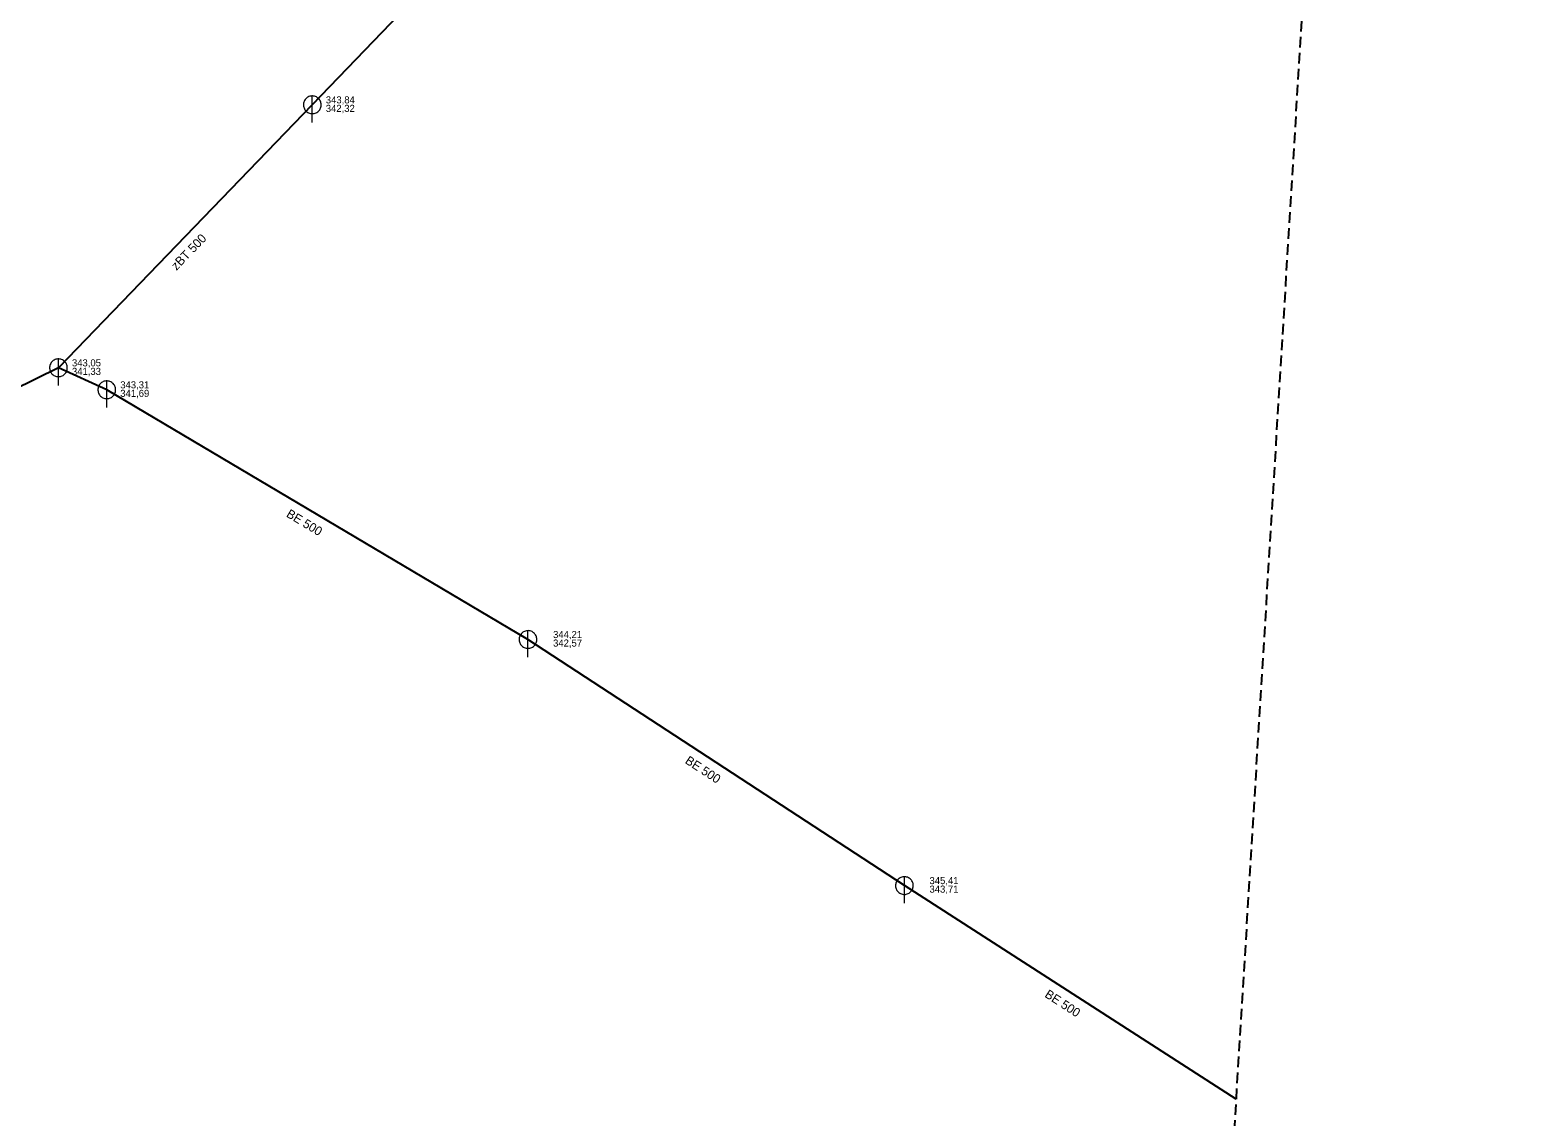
# Model space of a CAD drawing. Extents: x -724325 to -723665, y -972119 to -970722.
# Drawn here: x -724005.4 to -723835.3, y -971052.4 to -970929.9 of the extents above; entities that cross this region are included whole.
import ezdxf

# ---------------------------------------------------------------- set-up
doc = ezdxf.new("R2010")
doc.units = 0
doc.header["$LTSCALE"] = 0.4
doc.linetypes.add('MEDIUM_DASHED', pattern=[4.5, 3, -1.5])
for name, color, linetype, lineweight in [('1', 7, 'Continuous', 25), ('14', 7, 'Continuous', 25), ('22', 7, 'Continuous', 13)]:
    doc.layers.add(name, color=color, linetype=linetype, lineweight=lineweight)
doc.layers.add('19', color=7, linetype='Continuous')

msp = doc.modelspace()

# ---------------------------------------------------------------- linework, layer by layer
at = {"layer": '1', "linetype": 'MEDIUM_DASHED'}
msp.add_lwpolyline([(-724178.033, -970726.408), (-723849.368, -970722.221), (-723876.582, -971170.211), (-723665.148, -971503.063), (-723686.082, -972118.833), (-723917.752, -972118.833), (-723962.412, -971393.118), (-724325.27, -971133.535)], close=True, dxfattribs=at)
at = {"layer": '14'}
for p, q in [((-723942.149, -970905.61), (-723973.52, -970938.289)), ((-723973.52, -970938.289), (-724002.16, -970967.949)), ((-723996.71, -970970.43), (-724002.16, -970967.949)), ((-723949.19, -970998.59), (-723996.71, -970970.43)), ((-723906.719, -971026.34), (-723949.19, -970998.59)), ((-723869.306, -971050.437), (-723906.719, -971026.34))]:
    msp.add_line(p, q, dxfattribs=at)
msp.add_lwpolyline([(-724002.16, -970967.949), (-724038.379, -970985.76), (-724040.368, -970986.355)], dxfattribs=at)
at = {"layer": '22'}
for p, q in [((-723973.52, -970940.289), (-723973.519, -970937.289)), ((-724002.16, -970969.949), (-724002.159, -970966.949)), ((-723996.71, -970972.43), (-723996.709, -970969.43)), ((-723949.19, -971000.59), (-723949.189, -970997.59)), ((-723906.719, -971028.34), (-723906.718, -971025.34))]:
    msp.add_line(p, q, dxfattribs=at)
for points in [[(-723972.52, -970938.289), (-723972.525, -970938.18), (-723972.543, -970938.072), (-723972.573, -970937.966), (-723972.613, -970937.865), (-723972.665, -970937.768), (-723972.727, -970937.678), (-723972.799, -970937.595), (-723972.879, -970937.521), (-723972.967, -970937.455), (-723973.061, -970937.4), (-723973.161, -970937.355), (-723973.266, -970937.322), (-723973.373, -970937.3), (-723973.482, -970937.29), (-723973.592, -970937.292), (-723973.7, -970937.306), (-723973.807, -970937.331), (-723973.91, -970937.368), (-723974.008, -970937.417), (-723974.1, -970937.475), (-723974.186, -970937.544), (-723974.263, -970937.621), (-723974.332, -970937.707), (-723974.391, -970937.799), (-723974.439, -970937.897), (-723974.476, -970938), (-723974.502, -970938.107), (-723974.516, -970938.215), (-723974.519, -970938.325), (-723974.509, -970938.434), (-723974.488, -970938.541), (-723974.454, -970938.645), (-723974.41, -970938.745), (-723974.355, -970938.84), (-723974.289, -970938.928), (-723974.215, -970939.008), (-723974.132, -970939.08), (-723974.042, -970939.142), (-723973.946, -970939.194), (-723973.844, -970939.235), (-723973.739, -970939.265), (-723973.631, -970939.283), (-723973.521, -970939.289), (-723973.412, -970939.283), (-723973.304, -970939.265), (-723973.199, -970939.236), (-723973.097, -970939.195), (-723973, -970939.143), (-723972.91, -970939.081), (-723972.827, -970939.01), (-723972.752, -970938.93), (-723972.687, -970938.842), (-723972.631, -970938.748), (-723972.587, -970938.648), (-723972.553, -970938.544), (-723972.531, -970938.436), (-723972.521, -970938.327)], [(-724001.16, -970967.949), (-724001.165, -970967.84), (-724001.183, -970967.732), (-724001.213, -970967.626), (-724001.253, -970967.525), (-724001.305, -970967.428), (-724001.367, -970967.338), (-724001.439, -970967.255), (-724001.519, -970967.181), (-724001.607, -970967.115), (-724001.701, -970967.06), (-724001.801, -970967.015), (-724001.906, -970966.982), (-724002.013, -970966.96), (-724002.122, -970966.95), (-724002.232, -970966.952), (-724002.34, -970966.966), (-724002.447, -970966.991), (-724002.55, -970967.028), (-724002.648, -970967.077), (-724002.74, -970967.135), (-724002.826, -970967.204), (-724002.903, -970967.281), (-724002.972, -970967.367), (-724003.031, -970967.459), (-724003.079, -970967.557), (-724003.116, -970967.66), (-724003.142, -970967.767), (-724003.156, -970967.875), (-724003.159, -970967.985), (-724003.149, -970968.094), (-724003.128, -970968.201), (-724003.094, -970968.305), (-724003.05, -970968.405), (-724002.995, -970968.5), (-724002.929, -970968.588), (-724002.855, -970968.668), (-724002.772, -970968.74), (-724002.682, -970968.802), (-724002.586, -970968.854), (-724002.484, -970968.895), (-724002.379, -970968.925), (-724002.271, -970968.943), (-724002.161, -970968.949), (-724002.052, -970968.943), (-724001.944, -970968.925), (-724001.839, -970968.896), (-724001.737, -970968.855), (-724001.64, -970968.803), (-724001.55, -970968.741), (-724001.467, -970968.67), (-724001.392, -970968.59), (-724001.327, -970968.502), (-724001.271, -970968.408), (-724001.227, -970968.308), (-724001.193, -970968.204), (-724001.171, -970968.096), (-724001.161, -970967.987)], [(-723995.71, -970970.43), (-723995.715, -970970.321), (-723995.733, -970970.213), (-723995.763, -970970.107), (-723995.803, -970970.006), (-723995.855, -970969.909), (-723995.917, -970969.819), (-723995.989, -970969.736), (-723996.069, -970969.662), (-723996.157, -970969.596), (-723996.251, -970969.541), (-723996.351, -970969.496), (-723996.456, -970969.463), (-723996.563, -970969.441), (-723996.672, -970969.431), (-723996.782, -970969.433), (-723996.89, -970969.447), (-723996.997, -970969.472), (-723997.1, -970969.509), (-723997.198, -970969.558), (-723997.29, -970969.616), (-723997.376, -970969.685), (-723997.453, -970969.762), (-723997.522, -970969.848), (-723997.581, -970969.94), (-723997.629, -970970.038), (-723997.666, -970970.141), (-723997.692, -970970.248), (-723997.706, -970970.356), (-723997.709, -970970.466), (-723997.699, -970970.575), (-723997.678, -970970.682), (-723997.644, -970970.786), (-723997.6, -970970.886), (-723997.545, -970970.981), (-723997.479, -970971.069), (-723997.405, -970971.149), (-723997.322, -970971.221), (-723997.232, -970971.283), (-723997.136, -970971.335), (-723997.034, -970971.376), (-723996.929, -970971.406), (-723996.821, -970971.424), (-723996.711, -970971.43), (-723996.602, -970971.424), (-723996.494, -970971.406), (-723996.389, -970971.377), (-723996.287, -970971.336), (-723996.19, -970971.284), (-723996.1, -970971.222), (-723996.017, -970971.151), (-723995.942, -970971.071), (-723995.877, -970970.983), (-723995.821, -970970.889), (-723995.777, -970970.789), (-723995.743, -970970.685), (-723995.721, -970970.577), (-723995.711, -970970.468)], [(-723948.19, -970998.59), (-723948.195, -970998.481), (-723948.213, -970998.373), (-723948.243, -970998.267), (-723948.283, -970998.166), (-723948.335, -970998.069), (-723948.397, -970997.979), (-723948.469, -970997.896), (-723948.549, -970997.822), (-723948.637, -970997.756), (-723948.731, -970997.701), (-723948.831, -970997.656), (-723948.936, -970997.623), (-723949.043, -970997.601), (-723949.152, -970997.591), (-723949.262, -970997.593), (-723949.37, -970997.607), (-723949.477, -970997.632), (-723949.58, -970997.669), (-723949.678, -970997.718), (-723949.77, -970997.776), (-723949.856, -970997.845), (-723949.933, -970997.922), (-723950.002, -970998.008), (-723950.061, -970998.1), (-723950.109, -970998.198), (-723950.146, -970998.301), (-723950.172, -970998.408), (-723950.186, -970998.516), (-723950.189, -970998.626), (-723950.179, -970998.735), (-723950.158, -970998.842), (-723950.124, -970998.946), (-723950.08, -970999.046), (-723950.025, -970999.141), (-723949.959, -970999.229), (-723949.885, -970999.309), (-723949.802, -970999.381), (-723949.712, -970999.443), (-723949.616, -970999.495), (-723949.514, -970999.536), (-723949.409, -970999.566), (-723949.301, -970999.584), (-723949.191, -970999.59), (-723949.082, -970999.584), (-723948.974, -970999.566), (-723948.869, -970999.537), (-723948.767, -970999.496), (-723948.67, -970999.444), (-723948.58, -970999.382), (-723948.497, -970999.311), (-723948.422, -970999.231), (-723948.357, -970999.143), (-723948.301, -970999.049), (-723948.257, -970998.949), (-723948.223, -970998.845), (-723948.201, -970998.737), (-723948.191, -970998.628)], [(-723905.719, -971026.34), (-723905.724, -971026.231), (-723905.742, -971026.123), (-723905.772, -971026.017), (-723905.812, -971025.916), (-723905.864, -971025.819), (-723905.926, -971025.729), (-723905.998, -971025.646), (-723906.078, -971025.572), (-723906.166, -971025.506), (-723906.26, -971025.451), (-723906.36, -971025.406), (-723906.465, -971025.373), (-723906.572, -971025.351), (-723906.681, -971025.341), (-723906.791, -971025.343), (-723906.899, -971025.357), (-723907.006, -971025.382), (-723907.109, -971025.419), (-723907.207, -971025.468), (-723907.299, -971025.526), (-723907.385, -971025.595), (-723907.462, -971025.672), (-723907.531, -971025.758), (-723907.59, -971025.85), (-723907.638, -971025.948), (-723907.675, -971026.051), (-723907.701, -971026.158), (-723907.715, -971026.266), (-723907.718, -971026.376), (-723907.708, -971026.485), (-723907.687, -971026.592), (-723907.653, -971026.696), (-723907.609, -971026.796), (-723907.554, -971026.891), (-723907.488, -971026.979), (-723907.414, -971027.059), (-723907.331, -971027.131), (-723907.241, -971027.193), (-723907.145, -971027.245), (-723907.043, -971027.286), (-723906.938, -971027.316), (-723906.83, -971027.334), (-723906.72, -971027.34), (-723906.611, -971027.334), (-723906.503, -971027.316), (-723906.398, -971027.287), (-723906.296, -971027.246), (-723906.199, -971027.194), (-723906.109, -971027.132), (-723906.026, -971027.061), (-723905.951, -971026.981), (-723905.886, -971026.893), (-723905.83, -971026.799), (-723905.786, -971026.699), (-723905.752, -971026.595), (-723905.73, -971026.487), (-723905.72, -971026.378)]]:
    msp.add_lwpolyline(points, close=True, dxfattribs=at)

# ---------------------------------------------------------------- texts
at = {"layer": '1'}
for s, rotation, p in [('zBT 500 ', 46, (-723988.842, -970957.016)), ('BE 500', 329, (-723976.542, -970984.687)), ('BE 500', 327, (-723931.551, -971012.485)), ('BE 500', 327, (-723890.971, -971038.843))]:
    msp.add_text(s, height=1, rotation=rotation, dxfattribs=at).set_placement(p)
at = {"layer": '19'}
for s, p in [('343,84', (-723971.998, -970938.13)), ('342,32', (-723971.998, -970939.09)), ('343,05', (-724000.638, -970967.79)), ('341,33', (-724000.638, -970968.75)), ('343,31', (-723995.188, -970970.269)), ('341,69', (-723995.188, -970971.229)), ('344,21', (-723946.357, -970998.429)), ('342,57', (-723946.357, -970999.389)), ('345,41', (-723903.887, -971026.179)), ('343,71', (-723903.887, -971027.139))]:
    msp.add_text(s, height=0.8, dxfattribs=at).set_placement(p)

doc.saveas('drawing.dxf')
